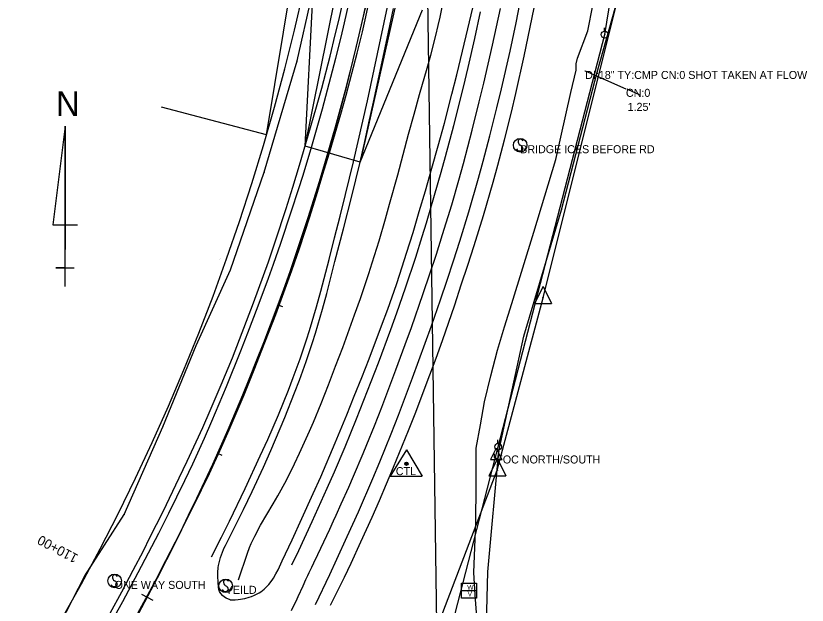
# Model space of a CAD drawing. Extents: x 1674300 to 1677920, y 225056 to 231852.
# Drawn here: x 1677124.2 to 1677618.5, y 228300.9 to 228668.9 of the extents above; entities that cross this region are included whole.
import ezdxf

# ---------------------------------------------------------------- set-up
doc = ezdxf.new("R2010")
doc.units = 0
for name, color, linetype in [('Default', 7, 'Continuous'), ('R_Annotation', 7, 'Continuous'), ('R_Axis', 7, 'Continuous'), ('R_Horz Alg', 7, 'Continuous'), ('R_Horz Alg Annot', 7, 'Continuous'), ('R_Proposed Const Limits_Fill', 7, 'Continuous'), ('R_ROW', 7, 'Continuous'), ('R_ROW Annot', 7, 'Continuous'), ('S_CROSS_DRAIN', 7, 'Continuous'), ('S_CROSS_DRAIN_ANNOT', 7, 'Continuous'), ('S_DITCHLINE', 7, 'Continuous'), ('S_DRG_PT_SYM', 7, 'Continuous'), ('S_DROP_INLET_ANNOT', 7, 'Continuous'), ('S_EDGE_PAVEMENT', 7, 'Continuous'), ('S_ELECTRIC_UTILITIES', 7, 'Continuous'), ('S_EXIST_ROW', 7, 'Continuous'), ('S_EXISTING_ALIGNMENT', 7, 'Continuous'), ('S_FIBER_OPTIC_CABLE', 7, 'Continuous'), ('S_MSC_PT_SYM', 7, 'Continuous'), ('S_PAVEMENT_CROWN', 7, 'Continuous'), ('S_PRIMARY_CTL', 7, 'Continuous'), ('S_SHOULDER', 7, 'Continuous'), ('S_SIGN', 7, 'Continuous'), ('S_SIGN_ANNOT', 7, 'Continuous'), ('S_UNDERGROUND_CABLE', 7, 'Continuous'), ('S_UTILITY_POLE', 7, 'Continuous'), ('S_UTILITY_POLE_ANNOT', 7, 'Continuous'), ('S_UTL_PT_SYM', 7, 'Continuous'), ('S_WATER_UTILITIES', 7, 'Continuous')]:
    doc.layers.add(name, color=color, linetype=linetype)

msp = doc.modelspace()

# ---------------------------------------------------------------- linework, layer by layer
at = {"layer": 'Default'}
for p, q in [((1677154.91, 228599.95), (1677147.22, 228538.41)), ((1677154.91, 228499.95), (1677154.91, 228599.95)), ((1677154.91, 228599.95), (1677154.91, 228523.03)), ((1677147.22, 228538.41), (1677162.6, 228538.41)), ((1677154.91, 228499.95), (1677154.91, 228523.03)), ((1677154.91, 228511.49), (1677149.14, 228511.49)), ((1677149.14, 228511.49), (1677160.68, 228511.49)), ((1677154.91, 228499.95), (1677154.91, 228511.49))]:
    msp.add_line(p, q, dxfattribs=at)
at = {"layer": 'R_Axis'}
for p, q in [((1677304.94, 228587.44), (1677324.42, 228684.4)), ((1677361.55, 228676.31), (1677339.23, 228577.45)), ((1677339.23, 228577.45), (1677304.94, 228587.44))]:
    msp.add_line(p, q, dxfattribs=at)
at = {"layer": 'R_Horz Alg'}
msp.add_arc((1675928.16, 228988.54), 1449, 296.0624, 0.80558, dxfattribs=at)
at = {"layer": 'R_Horz Alg Annot'}
msp.add_line((1677389.93, 228090.45), (1677377.01, 229008.91), dxfattribs=at)
for points in [[(1677322.2, 228582.41), (1677319.32, 228583.25)], [(1677290.88, 228487.25), (1677288.06, 228488.28)], [(1677253.07, 228394.47), (1677250.33, 228395.69)], [(1677202.77, 228307.82), (1677209.83, 228304.05)]]:
    msp.add_lwpolyline(points, dxfattribs=at)
at = {"layer": 'R_Proposed Const Limits_Fill'}
msp.add_line((1677304.94, 228587.44), (1677309.99, 228687.54), dxfattribs=at)
msp.add_lwpolyline([(1677339.23, 228577.45), (1677378.32, 228672.66)], dxfattribs=at)
at = {"layer": 'R_ROW'}
msp.add_lwpolyline([(1677280.82, 228594.47), (1677312.38, 228785.76), (1677312.38, 228785.76), (1677316.54, 229041.92), (1677294.58, 229181.63), (1677294.58, 229181.63)], dxfattribs=at)
at = {"layer": 'R_ROW Annot'}
msp.add_line((1677280.82, 228594.47), (1677215.14, 228611.93), dxfattribs=at)
at = {"layer": 'S_CROSS_DRAIN'}
msp.add_line((1677479.85, 228634.45), (1677505.31, 228623.28), dxfattribs=at)
at = {"layer": 'S_DITCHLINE'}
for points in [[(1677263.31, 228316.69), (1677268.91, 228333.35), (1677270.24, 228336.98), (1677271.23, 228339.35), (1677273.42, 228344.01), (1677277.08, 228350.84), (1677285, 228364.25), (1677287.81, 228369.15), (1677293.18, 228379.05), (1677298.24, 228389.08), (1677301.46, 228395.84), (1677307.62, 228409.48), (1677310.09, 228415.23), (1677314.88, 228426.78), (1677319.5, 228438.42), (1677323.95, 228450.13), (1677328.39, 228461.83), (1677335.84, 228482.23), (1677339.45, 228492.47), (1677344.65, 228507.89), (1677346.85, 228514.69), (1677351.07, 228528.35), (1677355.11, 228542.07), (1677357.71, 228551.25), (1677362.74, 228569.64), (1677366.12, 228582.28), (1677369.49, 228594.93), (1677372.96, 228607.55), (1677376.46, 228619.79), (1677381.16, 228636.11), (1677383.43, 228644.29), (1677386.61, 228656.6), (1677388.07, 228662.79), (1677389.21, 228667.99), (1677391.28, 228678.43)], [(1677412.08, 228293.34), (1677411.18, 228307.32), (1677410.29, 228321.3), (1677410.97, 228336.87), (1677411.65, 228352.45), (1677411.72, 228375.7), (1677411.79, 228398.95), (1677414.39, 228413.46), (1677417, 228427.97), (1677421, 228444.05), (1677425, 228460.14), (1677429.48, 228474.66), (1677433.97, 228489.17), (1677440.9, 228511.49), (1677447.83, 228533.8), (1677454.65, 228556.51), (1677461.47, 228579.22), (1677464.64, 228593.16), (1677467.81, 228607.09), (1677470.98, 228621.03), (1677474.15, 228634.96), (1677474.23, 228638.85), (1677475, 228642.39), (1677481.44, 228659.54), (1677484.58, 228675.24)], [(1677513.71, 228619.62), (1677506.9, 228622.64)]]:
    msp.add_lwpolyline(points, dxfattribs=at)
at = {"layer": 'S_DRG_PT_SYM'}
for points in [[(1677479.85, 228634.45), (1677479.85, 228634.5), (1677479.85, 228634.45), (1677479.8, 228634.45), (1677479.85, 228634.45), (1677479.85, 228634.4), (1677479.85, 228634.45), (1677479.9, 228634.45)], [(1677505.31, 228623.28), (1677505.31, 228623.33), (1677505.31, 228623.28), (1677505.26, 228623.28), (1677505.31, 228623.28), (1677505.31, 228623.23), (1677505.31, 228623.28), (1677505.36, 228623.28)], [(1677506.24, 228623.01), (1677506.24, 228623.06), (1677506.24, 228623.01), (1677506.19, 228623.01), (1677506.24, 228623.01), (1677506.24, 228622.96), (1677506.24, 228623.01), (1677506.29, 228623.01)]]:
    msp.add_lwpolyline(points, dxfattribs=at)
at = {"layer": 'S_EDGE_PAVEMENT'}
for points in [[(1677186.05, 228294.21), (1677190.97, 228303.18), (1677200.63, 228321.22), (1677207.04, 228333.55), (1677213.45, 228345.88), (1677219.73, 228358.28), (1677229.84, 228378.83), (1677234.74, 228389.18), (1677241.98, 228405.14), (1677246.65, 228415.85), (1677255.71, 228437.39), (1677264.73, 228459.73), (1677269.13, 228470.95), (1677275.59, 228487.82), (1677282.01, 228505.16), (1677285.14, 228513.85), (1677289.73, 228526.93), (1677296.49, 228547.02), (1677300.82, 228560.46), (1677303.63, 228569.45), (1677309.08, 228587.48), (1677315.76, 228610.85), (1677318.95, 228622.58), (1677324.09, 228642.38), (1677327.35, 228655.61), (1677329.47, 228664.46), (1677333.53, 228682.18)], [(1677311.4, 228301.34), (1677320.34, 228320.14), (1677324.74, 228329.57), (1677331.25, 228343.78), (1677338.18, 228359.24), (1677347.19, 228379.97), (1677351.56, 228390.39), (1677358.61, 228407.82), (1677363.18, 228419.49), (1677367.62, 228431.2), (1677372.06, 228442.92), (1677379.97, 228464.52), (1677383.84, 228475.35), (1677389.5, 228491.64), (1677393.54, 228503.78), (1677397.58, 228515.92), (1677401.47, 228528.12), (1677407.09, 228546.47), (1677413.2, 228567.53), (1677416.13, 228578.1), (1677420.36, 228594), (1677424.77, 228611.51), (1677427.58, 228623.22), (1677432.9, 228646.7), (1677436.65, 228664.42), (1677439.04, 228676.26)], [(1677246.51, 228331.03), (1677252.72, 228343.36), (1677257.69, 228353.46), (1677267.42, 228373.76), (1677276.91, 228394.14), (1677281.53, 228404.38), (1677288.22, 228419.85), (1677294.48, 228435.24), (1677297.46, 228442.99), (1677301.73, 228454.69), (1677305.72, 228466.49), (1677307.61, 228472.42), (1677311.95, 228487.11), (1677314.65, 228496.96), (1677319.82, 228516.72), (1677323.3, 228530.28), (1677326.77, 228543.84), (1677330.18, 228557.41), (1677335.16, 228577.8), (1677338.13, 228590.46), (1677340.98, 228603.14), (1677343.84, 228615.83), (1677348.08, 228635.39), (1677352.22, 228654.98), (1677356.37, 228674.57)], [(1677296.58, 228326.01), (1677300.87, 228335.06), (1677309.32, 228353.24), (1677318.65, 228373.88), (1677323.21, 228384.25), (1677329.89, 228399.87), (1677337.04, 228417.24), (1677341.68, 228428.87), (1677346.19, 228440.55), (1677350.69, 228452.24), (1677358.39, 228472.95), (1677362.14, 228483.34), (1677367.59, 228498.98), (1677373.97, 228518.18), (1677378.05, 228531.03), (1677380.69, 228539.62), (1677385.82, 228556.85), (1677389.94, 228571.29), (1677392.6, 228580.94), (1677397.76, 228600.29), (1677403.84, 228624.42), (1677406.74, 228636.52), (1677410.91, 228654.71), (1677414.49, 228671.28)]]:
    msp.add_lwpolyline(points, dxfattribs=at)
at = {"layer": 'S_ELECTRIC_UTILITIES'}
for p, q in [((1677492.08, 228657.14), (1677537.01, 228935.14)), ((1677425.49, 228399.8), (1677492.08, 228657.14)), ((1677343.16, 228080.48), (1677425.49, 228399.8))]:
    msp.add_line(p, q, dxfattribs=at)
at = {"layer": 'S_EXIST_ROW'}
for p, q in [((1677453.53, 228492.88), (1677507.28, 228707.44)), ((1677453.55, 228499.97), (1677448.26, 228489.33)), ((1677453.55, 228499.97), (1677458.78, 228489.33)), ((1677424.97, 228385.14), (1677453.53, 228492.88)), ((1677453.53, 228492.88), (1677453.53, 228492.88)), ((1677448.26, 228489.33), (1677458.78, 228489.33)), ((1677424.99, 228392.23), (1677419.7, 228381.6)), ((1677424.99, 228392.23), (1677430.22, 228381.6)), ((1677344.31, 228175.41), (1677424.97, 228385.14)), ((1677424.97, 228385.14), (1677424.97, 228385.14)), ((1677419.7, 228381.6), (1677430.22, 228381.6))]:
    msp.add_line(p, q, dxfattribs=at)
for centre, radius in [((1677453.53, 228492.88), 0.18), ((1677453.53, 228492.88), 0.09), ((1677424.97, 228385.14), 0.18), ((1677424.97, 228385.14), 0.09)]:
    msp.add_circle(centre, radius, dxfattribs=at)
msp.add_arc((1675926.71, 228989.39), 1410.53, 295.94359, 0.85682, dxfattribs=at)
at = {"layer": 'S_EXISTING_ALIGNMENT'}
for start, end in [(345.81316, 0.85682), (315.98862, 345.81316)]:
    msp.add_arc((1675926.71, 228989.39), 1450.53, start, end, dxfattribs=at)
at = {"layer": 'S_FIBER_OPTIC_CABLE'}
for p, q in [((1677299.85, 228640.69), (1677312.48, 228695.6)), ((1677487.34, 228633.72), (1677501.74, 228685.3)), ((1677279.39, 228571.17), (1677299.85, 228640.69)), ((1677465.1, 228547.8), (1677487.34, 228633.72)), ((1677258.19, 228510.33), (1677279.39, 228571.17)), ((1677441.54, 228468.97), (1677465.1, 228547.8)), ((1677236.83, 228463.03), (1677258.19, 228510.33)), ((1677425.99, 228396.98), (1677441.54, 228468.97)), ((1677216.05, 228412.32), (1677236.83, 228463.03)), ((1677191.77, 228357.44), (1677216.05, 228412.32)), ((1677419.05, 228321.79), (1677425.99, 228396.98)), ((1677167.35, 228319.14), (1677191.77, 228357.44)), ((1677416.97, 228249.14), (1677419.05, 228321.79)), ((1677150.44, 228286.49), (1677167.35, 228319.14))]:
    msp.add_line(p, q, dxfattribs=at)
at = {"layer": 'S_MSC_PT_SYM'}
msp.add_lwpolyline([(1677506.24, 228623.01), (1677506.24, 228623.06), (1677506.24, 228623.01), (1677506.19, 228623.01), (1677506.24, 228623.01), (1677506.24, 228622.96), (1677506.24, 228623.01), (1677506.29, 228623.01)], dxfattribs=at)
at = {"layer": 'S_PAVEMENT_CROWN'}
for points in [[(1677196.51, 228288.75), (1677204.2, 228302.85), (1677211.76, 228317.01), (1677217.9, 228328.74), (1677223.93, 228340.53), (1677229.95, 228352.32), (1677240.15, 228372.88), (1677245.11, 228383.23), (1677252.58, 228399.47), (1677257.41, 228410.37), (1677266.74, 228432.31), (1677273.54, 228448.96), (1677277.95, 228460.1), (1677286.55, 228482.48), (1677293.27, 228500.66), (1677296.53, 228509.78), (1677301.29, 228523.52), (1677307.81, 228543.39), (1677311.99, 228556.69), (1677316.04, 228570.04), (1677320.08, 228583.38), (1677323.61, 228595.39), (1677327.13, 228607.39), (1677330.53, 228619.43), (1677335.2, 228636.87), (1677337.44, 228645.62), (1677340.66, 228658.77), (1677345.2, 228678.58)], [(1677296.33, 228297.69), (1677298.28, 228301.57), (1677299.22, 228303.5), (1677300.6, 228306.39), (1677303.67, 228313.1), (1677305.44, 228316.94), (1677306.63, 228319.53), (1677307.44, 228321.25), (1677309.06, 228324.72), (1677310.3, 228327.34), (1677312.78, 228332.59), (1677320.28, 228348.45), (1677322.71, 228353.67), (1677324.32, 228357.15), (1677327.49, 228364.11), (1677332.15, 228374.55), (1677335.2, 228381.52), (1677341.15, 228395.52), (1677343.53, 228401.28), (1677348.21, 228412.85), (1677352.78, 228424.47), (1677357.22, 228436.16), (1677361.66, 228447.85), (1677367.48, 228463.7), (1677371.28, 228474.3), (1677378.69, 228495.54), (1677382.79, 228507.79), (1677386.88, 228520.03), (1677390.81, 228532.33), (1677396.47, 228550.86), (1677400.94, 228566.35), (1677403.8, 228576.72), (1677409.3, 228597.51), (1677413.73, 228615.14), (1677416.58, 228626.91), (1677422.04, 228650.52), (1677426.99, 228673.43)]]:
    msp.add_lwpolyline(points, dxfattribs=at)
at = {"layer": 'S_PRIMARY_CTL'}
for p, q in [((1677368.16, 228397.88), (1677358.13, 228381.37)), ((1677368.16, 228397.88), (1677377.98, 228381.37)), ((1677358.13, 228381.37), (1677377.98, 228381.37))]:
    msp.add_line(p, q, dxfattribs=at)
for radius in [1.04, 0.609, 0.344]:
    msp.add_circle((1677368.16, 228389.18), radius, dxfattribs=at)
at = {"layer": 'S_SHOULDER'}
for points in [[(1677183.02, 228295.95), (1677190.34, 228309.3), (1677197.49, 228322.74), (1677203.83, 228334.93), (1677207.99, 228343.09), (1677216.17, 228359.47), (1677226.3, 228380.39), (1677231.26, 228390.9), (1677240.91, 228411.95), (1677245.61, 228422.54), (1677252.47, 228438.49), (1677259.44, 228455.42), (1677263.95, 228466.77), (1677272.66, 228489.58), (1677278.93, 228506.75), (1677281.97, 228515.37), (1677286.42, 228528.33), (1677293.02, 228548.49), (1677297.26, 228561.99), (1677301.35, 228575.53), (1677305.44, 228589.07), (1677312.09, 228612.07), (1677315.28, 228623.6), (1677320.48, 228643.58), (1677323.76, 228656.95), (1677325.86, 228665.88), (1677329.89, 228683.79)], [(1677258.07, 228304.25), (1677261.15, 228304.28), (1677263.17, 228304.45), (1677267.15, 228305.12), (1677269.94, 228305.86), (1677271.32, 228306.32), (1677273.33, 228307.14), (1677276.2, 228308.66), (1677277.25, 228309.35), (1677279.22, 228310.9), (1677281.05, 228312.64), (1677282.18, 228313.88), (1677284.24, 228316.54), (1677285.09, 228317.8), (1677286.63, 228320.4), (1677288.02, 228323.09), (1677290.58, 228328.58), (1677296.73, 228341.79), (1677302.89, 228355.01), (1677310.02, 228370.65), (1677314.66, 228381.14), (1677323.69, 228402.22), (1677330.92, 228419.68), (1677335.64, 228431.36), (1677340.25, 228443.08), (1677344.87, 228454.8), (1677352.7, 228475.34), (1677356.49, 228485.66), (1677361.96, 228501.22), (1677364.13, 228507.66), (1677368.32, 228520.6), (1677372.34, 228533.59), (1677376.2, 228546.63), (1677380.07, 228559.67), (1677384.08, 228573.72), (1677388.09, 228587.76), (1677391.94, 228601.85), (1677396.65, 228619.99), (1677399.68, 228632.11), (1677405.55, 228656.41), (1677410.62, 228678.2)], [(1677258.04, 228304.22), (1677255.6, 228305.24), (1677254.55, 228305.85), (1677253.21, 228306.92), (1677252.15, 228308.18), (1677251.74, 228308.88), (1677251.47, 228309.49), (1677251.06, 228310.8), (1677250.79, 228312.2), (1677250.52, 228315.11), (1677250.34, 228319.29), (1677250.36, 228321.33), (1677250.6, 228324.34), (1677250.8, 228325.61), (1677251.36, 228328.15), (1677252.1, 228330.67), (1677253.95, 228335.71), (1677254.15, 228336.21), (1677255.21, 228338.26), (1677262.73, 228353.12), (1677266.4, 228360.58), (1677271.8, 228371.84), (1677278.85, 228387.15), (1677283.4, 228397.43), (1677286.37, 228404.31), (1677292.16, 228418.14), (1677298.33, 228433.58), (1677301.29, 228441.35), (1677305.53, 228453.06), (1677309.51, 228464.87), (1677311.38, 228470.81), (1677315.7, 228485.63), (1677318.39, 228495.57), (1677323.56, 228515.5), (1677328.81, 228535.84), (1677334.05, 228556.18), (1677339.03, 228576.58), (1677341.95, 228589.32), (1677344.74, 228602.09), (1677347.53, 228614.87), (1677350.68, 228629.49), (1677353.83, 228644.12), (1677356.97, 228658.75), (1677360.12, 228673.38)], [(1677320.78, 228300.93), (1677326.57, 228312.56), (1677329.42, 228318.39), (1677333.63, 228327.18), (1677339.81, 228340.42), (1677346.78, 228355.89), (1677351.32, 228366.26), (1677360.15, 228387.11), (1677369.47, 228409.91), (1677374, 228421.35), (1677380.61, 228438.59), (1677386.72, 228455.17), (1677390.68, 228466.26), (1677398.39, 228488.52), (1677402.48, 228500.84), (1677406.57, 228513.16), (1677410.53, 228525.53), (1677416.26, 228544.14), (1677422.36, 228565.08), (1677425.27, 228575.6), (1677429.45, 228591.41), (1677433.78, 228608.79), (1677436.54, 228620.41), (1677441.77, 228643.7), (1677445.59, 228661.79), (1677448.04, 228673.87)]]:
    msp.add_lwpolyline(points, dxfattribs=at)
at = {"layer": 'S_SIGN'}
for centre in [(1677439.27, 228588.08), (1677185.9, 228316.07), (1677255.3, 228313)]:
    msp.add_circle(centre, 4.24, dxfattribs=at)
for centre, radius, start, end in [((1677439.4, 228590.23), 1.62, 16.5258, 156.8957), ((1677440.44, 228590.33), 2.55, 167.1196, 241.9813), ((1677438.57, 228585.8), 2.38, 358.6529, 73.7063), ((1677439.01, 228586.68), 2.17, 204.641, 335.359), ((1677186.03, 228318.23), 1.62, 16.5258, 156.8957), ((1677187.07, 228318.33), 2.55, 167.1196, 241.9813), ((1677185.2, 228313.79), 2.38, 358.6529, 73.7063), ((1677256.46, 228315.26), 2.55, 167.1196, 241.9813), ((1677255.42, 228315.16), 1.62, 16.5258, 156.8957), ((1677185.64, 228314.67), 2.17, 204.641, 335.359), ((1677255.03, 228311.6), 2.17, 204.641, 335.359), ((1677254.59, 228310.72), 2.38, 358.6529, 73.7063)]:
    msp.add_arc(centre, radius, start, end, dxfattribs=at)
at = {"layer": 'S_UNDERGROUND_CABLE'}
for p, q in [((1677424.33, 228398.92), (1677420.8, 228391.83)), ((1677424.33, 228398.92), (1677427.81, 228391.83)), ((1677423.13, 228393.07), (1677423.13, 228395.51)), ((1677425.49, 228395.51), (1677425.49, 228393.07)), ((1677420.8, 228391.83), (1677427.81, 228391.83)), ((1677423.75, 228392.41), (1677423.13, 228393.07)), ((1677424.95, 228392.41), (1677423.75, 228392.41)), ((1677425.49, 228393.07), (1677424.95, 228392.41))]:
    msp.add_line(p, q, dxfattribs=at)
at = {"layer": 'S_UTILITY_POLE'}
for p, q in [((1677491.96, 228659.28), (1677491.96, 228661.39)), ((1677425.36, 228401.94), (1677425.36, 228404.05))]:
    msp.add_line(p, q, dxfattribs=at)
for centre in [(1677492.08, 228657.14), (1677425.49, 228399.8)]:
    msp.add_circle(centre, 2.13, dxfattribs=at)
at = {"layer": 'S_UTL_PT_SYM'}
for points in [[(1677492.08, 228657.14), (1677492.08, 228657.19), (1677492.08, 228657.14), (1677492.03, 228657.14), (1677492.08, 228657.14), (1677492.08, 228657.09), (1677492.08, 228657.14), (1677492.13, 228657.14)], [(1677299.85, 228640.69), (1677299.85, 228640.74), (1677299.85, 228640.69), (1677299.8, 228640.69), (1677299.85, 228640.69), (1677299.85, 228640.64), (1677299.85, 228640.69), (1677299.9, 228640.69)], [(1677487.34, 228633.72), (1677487.34, 228633.77), (1677487.34, 228633.72), (1677487.29, 228633.72), (1677487.34, 228633.72), (1677487.34, 228633.67), (1677487.34, 228633.72), (1677487.39, 228633.72)], [(1677279.39, 228571.17), (1677279.39, 228571.22), (1677279.39, 228571.17), (1677279.34, 228571.17), (1677279.39, 228571.17), (1677279.39, 228571.12), (1677279.39, 228571.17), (1677279.44, 228571.17)], [(1677465.1, 228547.8), (1677465.1, 228547.85), (1677465.1, 228547.8), (1677465.05, 228547.8), (1677465.1, 228547.8), (1677465.1, 228547.75), (1677465.1, 228547.8), (1677465.15, 228547.8)], [(1677258.19, 228510.33), (1677258.19, 228510.38), (1677258.19, 228510.33), (1677258.14, 228510.33), (1677258.19, 228510.33), (1677258.19, 228510.28), (1677258.19, 228510.33), (1677258.24, 228510.33)], [(1677441.54, 228468.97), (1677441.54, 228469.02), (1677441.54, 228468.97), (1677441.49, 228468.97), (1677441.54, 228468.97), (1677441.54, 228468.92), (1677441.54, 228468.97), (1677441.59, 228468.97)], [(1677236.83, 228463.03), (1677236.83, 228463.08), (1677236.83, 228463.03), (1677236.78, 228463.03), (1677236.83, 228463.03), (1677236.83, 228462.98), (1677236.83, 228463.03), (1677236.88, 228463.03)], [(1677216.05, 228412.32), (1677216.05, 228412.37), (1677216.05, 228412.32), (1677216, 228412.32), (1677216.05, 228412.32), (1677216.05, 228412.27), (1677216.05, 228412.32), (1677216.1, 228412.32)], [(1677425.49, 228399.8), (1677425.49, 228399.85), (1677425.49, 228399.8), (1677425.44, 228399.8), (1677425.49, 228399.8), (1677425.49, 228399.75), (1677425.49, 228399.8), (1677425.54, 228399.8)], [(1677425.99, 228396.98), (1677425.99, 228397.03), (1677425.99, 228396.98), (1677425.94, 228396.98), (1677425.99, 228396.98), (1677425.99, 228396.93), (1677425.99, 228396.98), (1677426.04, 228396.98)], [(1677191.77, 228357.44), (1677191.77, 228357.49), (1677191.77, 228357.44), (1677191.72, 228357.44), (1677191.77, 228357.44), (1677191.77, 228357.39), (1677191.77, 228357.44), (1677191.82, 228357.44)], [(1677419.05, 228321.79), (1677419.05, 228321.84), (1677419.05, 228321.79), (1677419, 228321.79), (1677419.05, 228321.79), (1677419.05, 228321.74), (1677419.05, 228321.79), (1677419.1, 228321.79)], [(1677167.35, 228319.14), (1677167.35, 228319.19), (1677167.35, 228319.14), (1677167.3, 228319.14), (1677167.35, 228319.14), (1677167.35, 228319.09), (1677167.35, 228319.14), (1677167.4, 228319.14)]]:
    msp.add_lwpolyline(points, dxfattribs=at)
at = {"layer": 'S_WATER_UTILITIES'}
for p, q in [((1677402.64, 228314.69), (1677412.06, 228314.69)), ((1677402.64, 228305.27), (1677402.64, 228314.69)), ((1677412.06, 228314.69), (1677412.06, 228305.27)), ((1677402.64, 228310), (1677412.06, 228310)), ((1677412.06, 228305.27), (1677402.64, 228305.27))]:
    msp.add_line(p, q, dxfattribs=at)

# ---------------------------------------------------------------- texts
at = {"layer": 'Default'}
msp.add_text('N', height=15.38, rotation=360, dxfattribs=at).set_placement((1677149.28, 228606.36))
at = {"layer": 'R_Annotation'}
msp.add_text('EXIST. R/W', height=0.12, rotation=69.8931, dxfattribs=at).set_placement((1677251.6, 228516.55))
at = {"layer": 'R_Horz Alg Annot'}
msp.add_text('110+00', height=6, rotation=151.895, dxfattribs=at).set_placement((1677163.61, 228332.13))
at = {"layer": 'R_ROW Annot'}
for s, p in [("40.11'", (1677225.16, 228609.35)), ('+00', (1677225.08, 228609.19))]:
    msp.add_text(s, height=0.12, rotation=163.458, dxfattribs=at).set_placement(p)
at = {"layer": 'S_CROSS_DRAIN_ANNOT'}
for s, p in [('DI:18" TY:CMP CN:0 SHOT TAKEN AT FLOW', (1677479.85, 228629.45)), ('CN:0', (1677505.31, 228618.28))]:
    msp.add_text(s, height=5, rotation=360, dxfattribs=at).set_placement(p)
at = {"layer": 'S_DROP_INLET_ANNOT'}
msp.add_text("1.25'", height=5, rotation=360, dxfattribs=at).set_placement((1677506.38, 228609.54))
at = {"layer": 'S_PRIMARY_CTL'}
msp.add_text('CTL', height=5, rotation=360, dxfattribs=at).set_placement((1677361.57, 228382.11))
at = {"layer": 'S_SIGN_ANNOT'}
for s, p in [('BRIDGE ICES BEFORE RD', (1677439.27, 228583.08)), ('ONE WAY SOUTH', (1677185.9, 228311.07)), ('YEILD', (1677255.3, 228308))]:
    msp.add_text(s, height=5, rotation=360, dxfattribs=at).set_placement(p)
at = {"layer": 'S_UTILITY_POLE_ANNOT'}
msp.add_text('FOC NORTH/SOUTH', height=5, rotation=360, dxfattribs=at).set_placement((1677424.33, 228389.39))
at = {"layer": 'S_WATER_UTILITIES'}
for s, p in [('W', (1677406.19, 228310.53)), ('V', (1677406.43, 228306.47))]:
    msp.add_text(s, height=3, rotation=360, dxfattribs=at).set_placement(p)

doc.saveas('drawing.dxf')
